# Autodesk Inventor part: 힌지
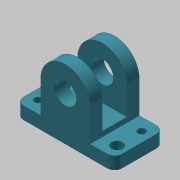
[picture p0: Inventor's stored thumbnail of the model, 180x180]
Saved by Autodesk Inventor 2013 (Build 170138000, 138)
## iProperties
Created: 2019-09
Part Number: 힌지
Material: 알루미늄 6061
Document SubType Name: Modeling
Designer: mduedu
Density: 2.71 g/cm^3
Mass: 20.7756 g
Surface Area: 43.3328 cm^2
Volume: 7.66629 cm^3
Author: mduedu
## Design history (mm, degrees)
sketch "스케치1"
  geometry: L1 (-20, 0)-(20, 0); L2 (20, 0)-(20, 5); L3 (-20, 5)-(-20, 0); L4 (10, 5)-(10, 18); L5 (-10, 18)-(-10, 5); L6 (20, 5)-(10, 5); L7 (-10, 5)-(-20, 5); C1 r 4.5 at (0, 18); A1 r 10 centre (0, 18) between (10, 18) and (-10, 18); 2 further points
  constraints: 14 end point, 4 parallel, 2 centre point, 2 coincident, 2 point on circle, 2 tangent, 1 collinear, 1 horizontal, 1 midpoint, 1 perpendicular, 1 vertical, 1 vertical alignment
  dimensions: "d0" = 40 distance of L1.start L1.end; "d2" = 20 distance between parallel lines of L4 L5; "d3" = 18 distance from line of L1 A1.centre; "d4" = 5 distance of L1.end L2.end; "d5" = 9 diameter of C1
extrude "돌출1" new body sketch "스케치1" stored distance "d6" = 20; taper "d7" = 0 deg
sketch "스케치2"
  geometry: L1 (7, 5)-(37, 5); L2 (37, 5)-(37, -5); L3 (37, -5)-(7, -5); L4 (7, -5)-(7, 5); L5 (0, 10)-(0, -10) reference; 2 further points
  constraints: 8 end point, 2 parallel, 1 horizontal, 1 horizontal alignment, 1 midpoint, 1 perpendicular
  dimensions: "d8" = 7 distance between parallel lines of L5 L4; "d9" = 10 distance of L1.end L2.end; "d10" = 30 distance of L2.end L3.end
extrude "돌출2" cut sketch "스케치2" stored distance "d11" = 20; taper "d12" = 0 deg
sketch "스케치3"
  geometry: 3 further points
  dimensions: "d13" = 16 horizontal distance of point (6, 15) point (-10, 10); "d14" = 32 horizontal distance of point (-26, 5) point (6, 15); "d15" = 5 vertical distance of point (6, 15) point (-10, 10); "d16" = 10 vertical distance of point (-26, 5) point (6, 15)
hole "구멍1" sketch "스케치3" at (6, 15), (-26, 5) diameter "d17" = 3; stored, may be unused: countersink angle "d21" = 90 deg, drill point angle "d23" = 118 deg; dims "d18" = 6, "d19" = 4, "d20" = 2, "d22" = 8
sketch "스케치4"
  geometry: C1 r 1.5 at (6, 15) reference; C2 r 1.5 at (-26, 5) reference; 3 further points
  constraints: 2 horizontal alignment, 2 vertical alignment
hole "구멍2" sketch "스케치4" at (-26, 15), (6, 5) diameter "d24" = 4.5; stored, may be unused: countersink angle "d28" = 90 deg, drill point angle "d30" = 118 deg; dims "d25" = 6, "d26" = 4, "d27" = 2, "d29" = 8
fillet "모깎기1" dims "d31" = 3
node "솔리드1"
